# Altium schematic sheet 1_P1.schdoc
size 431 x 309 mm; Symbol: Sheet-Symbol_A3; Device: Sheet-Symbol_A3; Company: 嘉立创EDA; Version: V1.0; Page Size: A3; @Project Name: 辉光管时钟成品; @Page Count: 1; @Update Date: 2024-01-18; @Create Date: 2024-01-13; @Schematic Name: 电源部分; @Page No: 1; @Page Name: P1
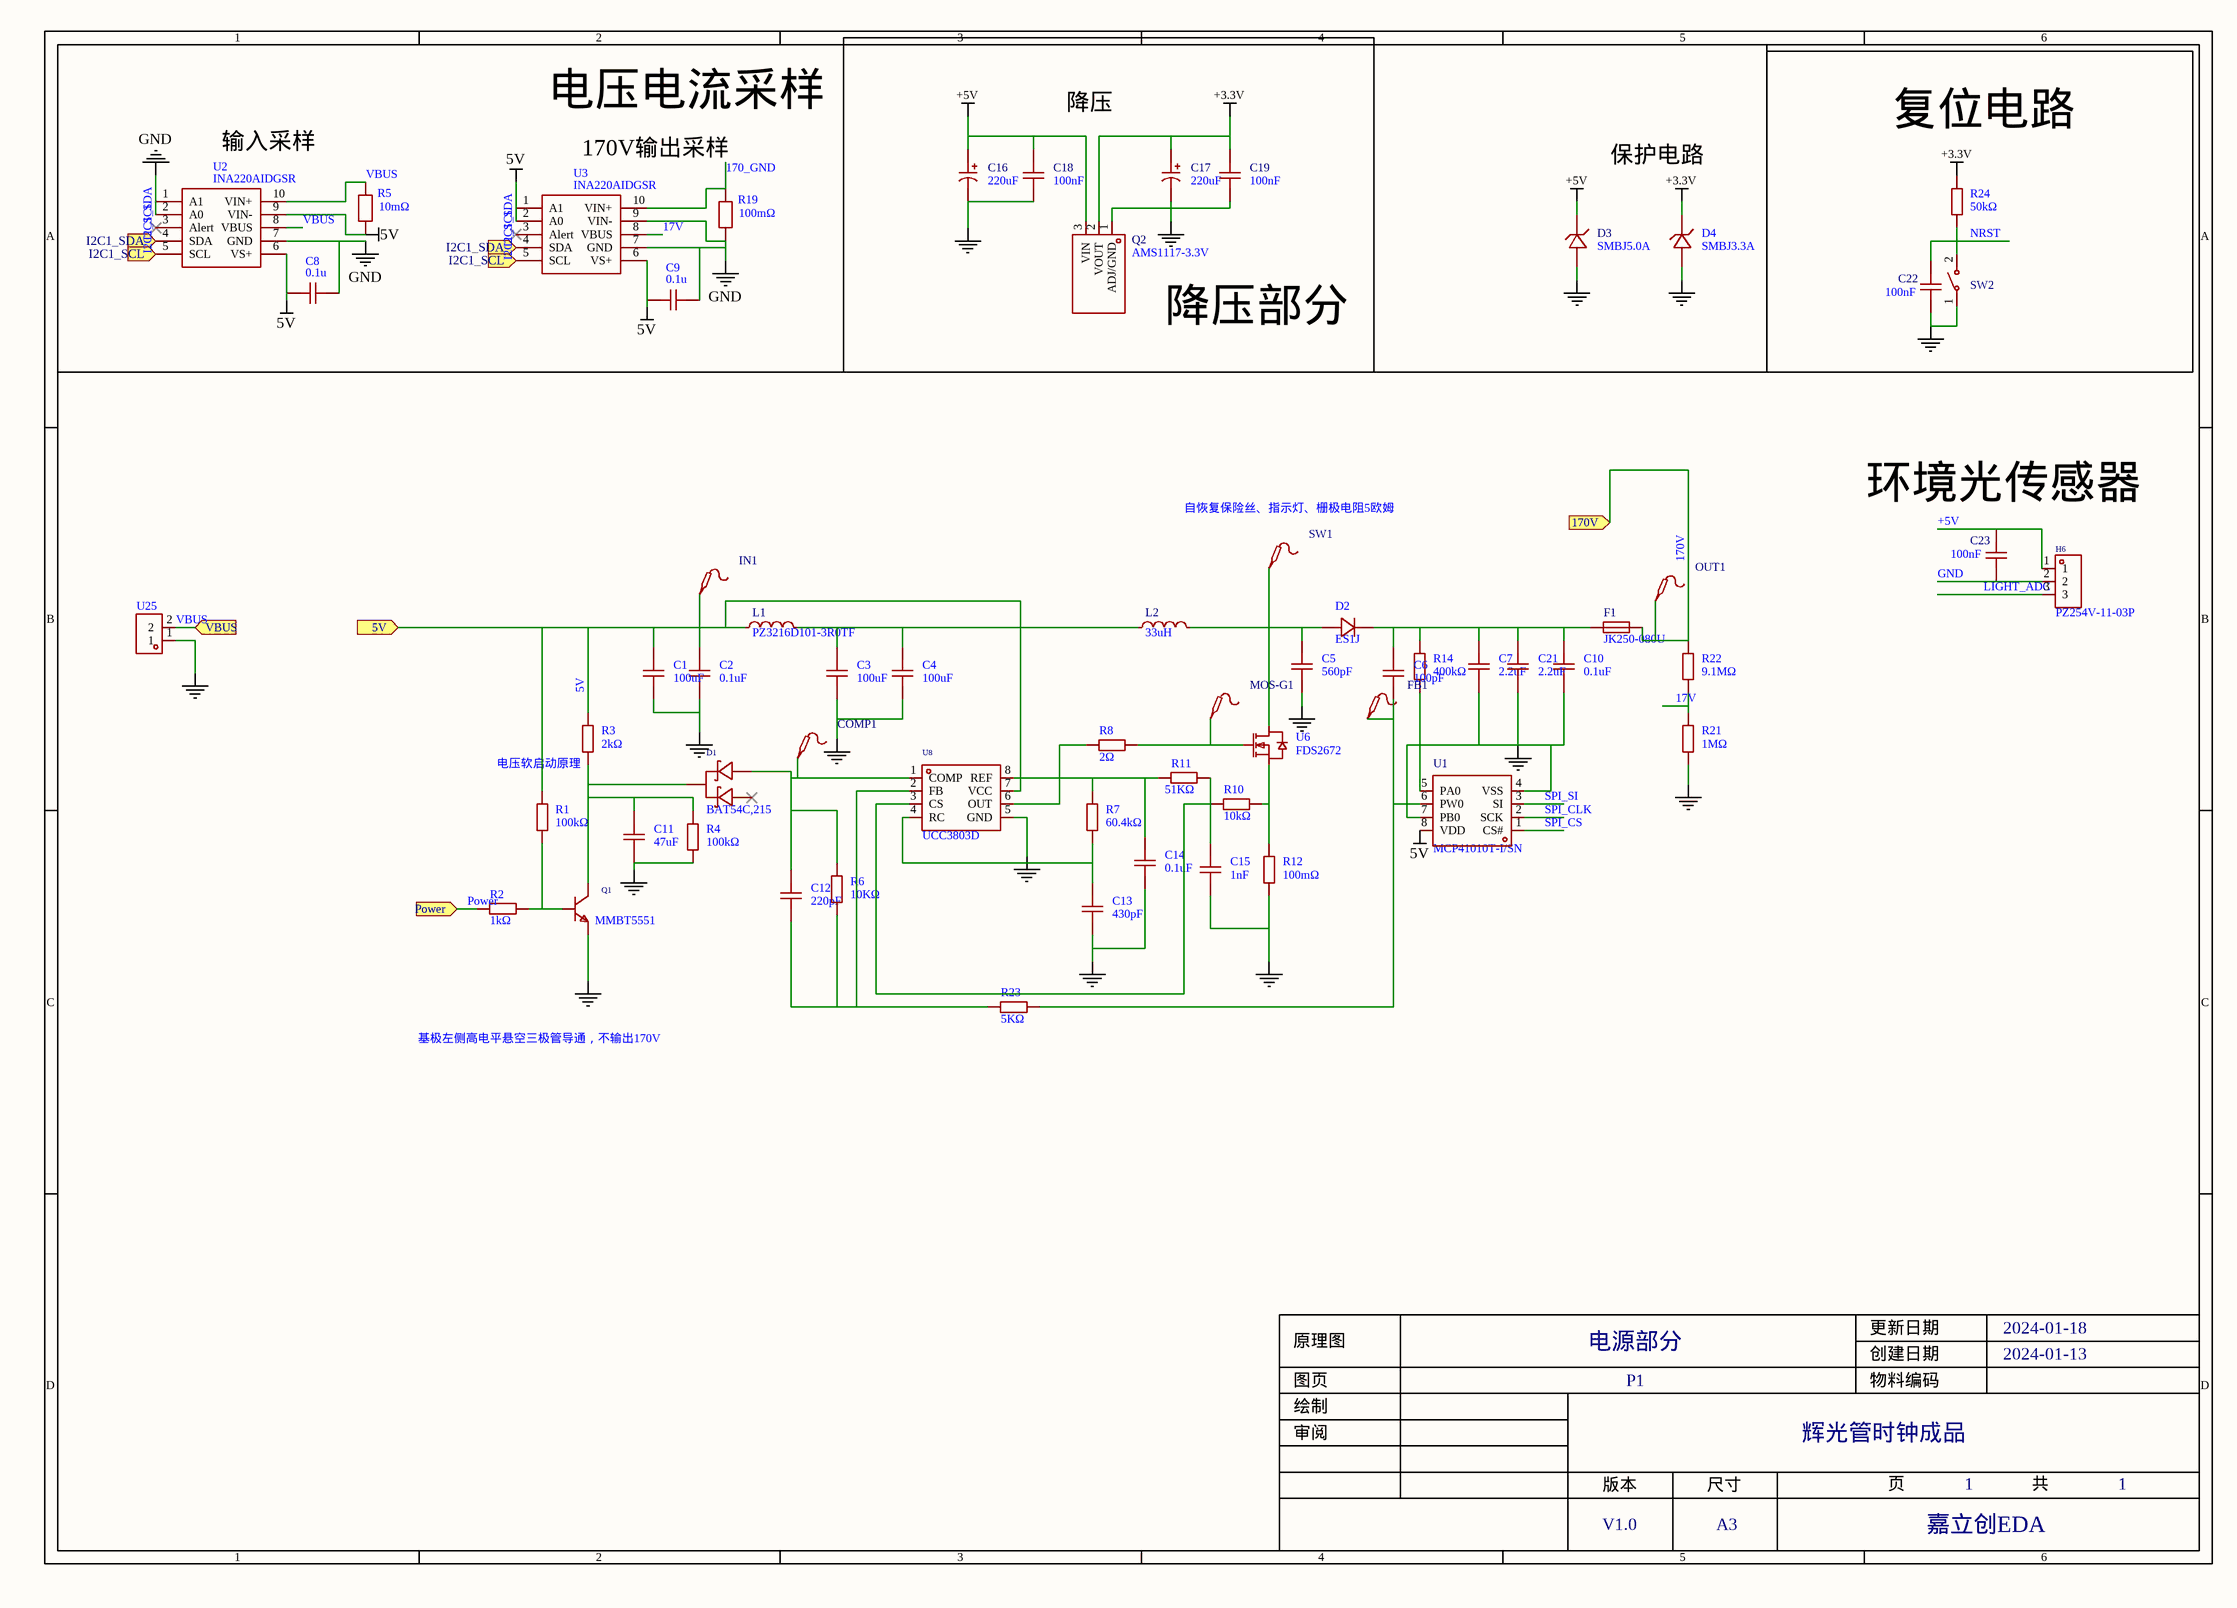
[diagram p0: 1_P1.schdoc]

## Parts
C1  100uF  [c1206]
C2  0.1uF  [c0603]
C3  100uF  [c1206]
C4  100uF  [c1206]
C5  560pF  [c1206]
C6  100pF  [C0805]
C7  2.2uF  [c1210]
C8  0.1u  [C0603]
C9  0.1u  [C0603]
C10  0.1uF  [c1206]
C11  47uF  [c0603]
C12  220pF  [c0603]
C13  430pF  [c0603]
C14  0.1uF  [c0603]
C15  1nF  [c0603]
C16  220uF  [CAP-SMD_BD6.3-L6.6-W6.6-FD]
C17  220uF  [CAP-SMD_BD6.3-L6.6-W6.6-FD]
C18  100nF  [C0603]
C19  100nF  [C0603]
C21  2.2uF  [c1210]
C22  100nF  [C0603]
C23  100nF  [C0603]
COMP1  (no value)  [Test-Point-0.5mm]
D1  BAT54C,215  [SOT-23-3_L2.9-W1.6-P1.90-LS2.8-BR]
D2  ES1J  [sod-123_l2.7-w1.6-ls3.6-rd]
D3  SMBJ5.0A  [SMB_L4.4-W3.6-LS5.3-RD]
D4  SMBJ3.3A  [SMB_L4.6-W3.6-LS5.3-RD]
F1  JK250-080U  [FUSE-TH_L5.8-W3.8-P5.10-D0.8]
FB1  (no value)  [Test-Point-0.5mm]
H6  PZ254V-11-03P  [HDR-TH_3P-P2.54-V-M]
IN1  (no value)  [Test-Point-0.5mm]
L1  PZ3216D101-3R0TF  [l0603]
L2  33uH  [33uh功率电感]
MOS-G1  (no value)  [Test-Point-0.5mm]
OUT1  (no value)  [Test-Point-0.5mm]
Q1  MMBT5551  [SOT-23-3_L2.9-W1.3-P1.90-LS2.4-BR]
Q2  AMS1117-3.3V  [SOT-89-3_L4.5-W2.5-P1.50-LS4.2-BR]
R1  100kΩ  [r0603]
R2  1kΩ  [r0603]
R3  2kΩ  [r0603]
R4  100kΩ  [r0603]
R5  10mΩ  [R0805]
R6  10KΩ  [r0603]
R7  60.4kΩ  [r0603]
R8  2Ω  [r0603]
R10  10kΩ  [r0603]
R11  51KΩ  [r0603]
R12  100mΩ  [R0805]
R14  400kΩ  [r0603]
R19  100mΩ  [R0805]
R21  1MΩ  [r0603]
R22  9.1MΩ  [r0603]
R23  5KΩ  [r0603]
R24  50kΩ  [r0603]
SW1  (no value)  [Test-Point-0.5mm]
SW2  TS-1088R-02026  [SW-SMD_L3.9-W3.0-P4.45]  (value not drawn)
U1  MCP41010T-I/SN  [SOIC-8_L4.9-W3.9-P1.27-LS6.0-BL]
U2  INA220AIDGSR  [VSSOP-10_L3.0-W3.0-P0.50-LS4.9-BL]
U3  INA220AIDGSR  [VSSOP-10_L3.0-W3.0-P0.50-LS4.9-BL]
U6  FDS2672  [SO-8_L4.9-W3.9-P1.27-LS6.0-BL]
U8  UCC3803D  [SOIC-8_L4.9-W3.9-P1.27-LS6.0-BL]
U25  (no value)  [2.54mm1*2]

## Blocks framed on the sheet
电压电流采样: C8 C9 R5 R19 U2 U3
降压部分: C16-C19 Q2
保护电路: D3 D4
复位电路: C22 R24 SW2

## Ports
5V (in), 170V (in), I2C1_SCL (in), I2C1_SDA (in), Power (in), VBUS (in)

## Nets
5V: C1.2 C2.2 C8.2 C9.2 IN1.1 L1.1 R1.2 R3.2 R5.1 U1.8(VDD) U2.6(VS+) U2.9(VIN-) U3.1(A1) U3.2(A0) U3.6(VS+) U8.7(VCC) ; port 5V
+3.3V: C17.1 C19.2 D4.1 Q2.2(VOUT) R24.2
+5V: C16.1 C18.2 C23.2 D3.1(C) H6.1 Q2.3(VIN)
GND: C1.1 C2.1 C3.1 C4.1 C5.1 C7.1 C8.1 C9.1 C10.1 C11.1 C13.1 C14.1 C15.1 C16.2 C17.2 C18.1 C19.1 C21.1 C22.1 C23.1 D3.2(A) D4.2 H6.2 Q1.2(E) Q2.1(ADJ/GND) R4.1 R12.1 R19.1 R21.2 SW2.1 U1.4(VSS) U1.7(PB0) U2.1(A1) U2.2(A0) U2.7(GND) U3.7(GND) U3.9(VIN-) U8.5(GND) U25.1
17V: R21.1 R22.2 U3.8(VBUS)
170_GND: R19.2 U3.10(VIN+)
170V: F1.2 OUT1.1 R22.1 ; port 170V
I2C1_SCL: U2.5(SCL) U3.5(SCL) ; port I2C1_SCL
I2C1_SDA: U2.4(SDA) U3.4(SDA) ; port I2C1_SDA
LIGHT_ADC: H6.3
NRST: C22.2 R24.1 SW2.2
Power: R2.2 ; port Power
SPI_CLK: U1.2(SCK)
SPI_CS: U1.1(CS#)
SPI_SI: U1.3(SI)
VBUS: R5.2 U2.8(VBUS) U2.10(VIN+) U25.2 ; port VBUS
NetC3_2: C3.2 C4.2 L1.2 L2.1
NetC5_2: C5.2 D2.2(A) L2.2 SW1.1 U6.5(D) U6.6(D) U6.7(D) U6.8(D)
NetC6_1: C6.1 FB1.1 R23.1 U1.6(PW0)
NetC6_2: C6.2 C7.2 C10.2 C21.2 D2.1(K) F1.1 R14.2
NetC11_2: C11.2 D1.3(K) Q1.3(C) R3.1 R4.2
NetC12_1: C12.1 R6.1 R23.2 U8.2(FB)
NetC12_2: C12.2 COMP1.1 D1.1(A) R6.2 U8.1(COMP)
NetC13_2: C13.2 R7.1 U8.4(RC)
NetC14_2: C14.2 R7.2 R11.2 U8.8(REF)
NetC15_2: C15.2 R10.2 R11.1 U8.3(CS)
NetMOS-G1_1: MOS-G1.1 R8.1 U6.4(G)
NetQ1_1: Q1.1(B) R1.1 R2.1
NetR8_2: R8.2 U8.6(OUT)
NetR10_1: R10.1 R12.2 U6.1(S) U6.2(S) U6.3(S)
NetR14_1: R14.1 U1.5(PA0)

Not connected (* = marked no-connect by the designer): D1 2(A)*; U2 3(Alert)*; U3 3(Alert)*

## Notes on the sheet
- 降压
- (near U2) 输入采样
- 170V输出采样
- (near SW1) 自恢复保险丝、指示灯、栅极电阻5欧姆
- (near C23) 环境光传感器
- 电压软启动原理
- 基极左侧高电平悬空三极管导通，不输出170V

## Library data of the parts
C1-C6 C10-C15 = CC0805KRX7R9BB104: Manufacturer: YAGEO(国巨); Symbol: capacitance; Add into BOM: yes; Tolerance: ±10%; Voltage Rated: 50V; Temperature Coefficient: X7R
C7 C21 = CC0805KRX7R9BB104: Manufacturer: YAGEO(国巨); Symbol: capacitance; Add into BOM: yes; Tolerance: ±10%; Voltage Rated: 200V; Temperature Coefficient: X7R
C8 C9 = 0.1u: Convert to PCB: yes
C16 C17 = RVT220UF10V67RV0037: Manufacturer: KNSCHA(科尼盛); Add into BOM: yes; Tolerance: ±20%; Rated Voltage: 10V; Ripple Current: 69mA@120Hz; φD: 6.3mm; L: 5.4mm; Lifetime @ Temp: 2000hrs@105℃
C18 C19 C22 C23 = CC0603KRX7R9BB104: Manufacturer: YAGEO(国巨); Add into BOM: yes; Tolerance: ±10%; Voltage Rated: 50V; Temperature Coefficient: X7R
COMP1 FB1 IN1 MOS-G1 OUT1 SW1 = Test-Point: Add into BOM: yes
D1 = BAT54C,215: Manufacturer: Nexperia(安世); Add into BOM: yes; Diode Configuration: 1对共阴极; Reverse Voltage (Vr): 30V; Average Rectified Current (Io): 200mA; Forward Voltage (Vf@If): 800mV@100mA; Reverse Leakage Current (Ir): 2uA@25V
D2 = ES1J_C691230: Manufacturer: DIODES(美台); Symbol: 1n4007_c9900004759; Add into BOM: yes
D3 = SMBJ5.0A_C726811: Manufacturer: TWGMC(台湾迪嘉); Add into BOM: yes
D4 = SMBJ3.3A_C362089: Manufacturer: JKSEMI(金开盛); Add into BOM: yes; Unidirectional Channels: 1; Bidirectional Channels: 0; Reverse Stand-Off Voltage (Vrwm): 3.3V; Breakdown Voltage: 4.1V; Maximum Clamping Voltage: 7.3V; Peak Pulse Power Dissipation (Ppp)@10/1000us: 600W
F1 = JK250-080U: Manufacturer: JK(金科); Symbol: JK250-080U_C369127; Add into BOM: yes; Operating Voltage (Max): 250V; Current Rating (Max): 3A; Hold Current: 80mA; Trip Current: 160mA; Maximum Time to Trip: 500ms
H6 = PZ254V-11-03P: Manufacturer: XFCN(兴飞); Symbol: PZ254V-11-03P_C2937625; Add into BOM: yes; Pitch: 2.54mm; Pin Structure: 1x3P; Circluar Pins/Square Pins: 方针; Current Rating (Max): 3A; Voltage Rating (Max): 250V
L1 = PZ3216D101-3R0TF: Manufacturer: Sunlord(顺络); Symbol: sdfl1608s100ktf; Add into BOM: yes; Impedance @ Frequency: 100Ω@100MHz; Tolerance: ±25%; Current Rating: 3A; Circuits: 1; Value: 10uH
L2 = CXP0630-330M-AG(33uh): Manufacturer: DMBJ(振宝佳); Symbol: sdfl1608s100ktf; Add into BOM: yes; Type: 一体成型电感; Tolerance: ±20%; Rated Current: 2A; Saturation Current (Isat): 2.5A; DC Resistance (DCR): 240mΩ
Q1 = MMBT5551_C2145: Manufacturer: CJ(江苏长电/长晶); Symbol: bcx70ke6327htsa1; Add into BOM: yes; Transistor Type: NPN; Collector-Emitter Breakdown Voltage (Vceo): 160V; Collector Current (Ic): 600mA; Power Dissipation (Pd): 300mW; Collector Cut-Off Current (Icbo): 50nA; Collector-Emitter Saturation Voltage (VCE(sat)@Ic,Ib): 200mV@50mA,5mA; DC Current Gain (hFE@Ic,Vce): 200@10mA,5V; Transition Frequency (fT): 100MHz
Q2 = AMS1117-3.3V_C5120796: Manufacturer: MSKSEMI(美森科); Add into BOM: yes; Output Type: 固定; Maximum Input Voltage: 18V; Output Voltage: 3.3V; MAX Output Current: 1A; Dropout Voltage: 1.4V@(1A); standby current: 12mA; Output Polarity: 正极; Number of Outputs: 1
R1-R4 R6-R8 R10 R11 R14 R21-R24 = 0805W8F1002T5E_C17414: Manufacturer: UNI-ROYAL(厚声); Symbol: 电阻; Add into BOM: yes; Tolerance: ±1%; Power(Watts): 125mW; Temperature Coefficient: ±100ppm/℃; Overload Voltage (Max): 150V
R5 R19 = 5mΩ: Convert to PCB: yes; Origin Footprint: R1206
R12 = RL10FTNR160: Manufacturer: 大毅科技; Symbol: 电阻; Add into BOM: yes; Tolerance: ±1%; Power(Watts): 125mW; Temperature Coefficient: ±100ppm/℃; Overload Voltage (Max): 150V
SW2 = TS-1088R-02026: Manufacturer: XUNPU(讯普); Add into BOM: yes; Circuit: 单刀单掷; Actuator Style: 圆形按钮; Switch Length: 3.9mm; Switch Width: 2.93mm; Switch Height: 2mm; Contact Current: 50mA; Voltage Rating (DC): 12V
U1 = MCP41010T-I/SN: Manufacturer: MICROCHIP(美国微芯); Add into BOM: yes; Supply Voltage: 2.7V~5.5V; Resistance Value (Ohms): 10kΩ; Number of Taps: 256; Temperature Coefficient (Typ): 800ppm/℃; Precision: ±20%; Number of Channels: 1; Interface Type: SPI
U2 U3 = INA220AIDGSR: Manufacturer: TI(德州仪器); Symbol: INA220; Add into BOM: yes; Origin Footprint: MSOP-10_L3.0-W3.0-P0.50-LS5.0-BL
U6 = FDS2672: Manufacturer: onsemi(安森美); Add into BOM: yes; Drain Source Voltage (Vdss): 200V; Continuous Drain Current (Id): 3.9A; Power Dissipation (Pd): 2.5W; Drain Source On Resistance (RDS(on)@Vgs,Id): 70mΩ@10V,3.9A; Gate Threshold Voltage (Vgs(th)@Id): 4V@250uA; Total Gate Charge (Qg@Vgs): 46nC@10V; Input Capacitance (Ciss@Vds): 2.535nF@100V
U8 = UCC3803D: Manufacturer: TI(德州仪器); Symbol: ucc3803dtrg4; Add into BOM: yes; Function: 升压型；降压型；升降压型; Number of Outputs: 1; Input Voltage: 3.6V~12V; Synchronous Rectification: 否; Topology: 反激式；降压式；正激式；升压式; Switching Frequency: 31kHz; Duty Cycle (Max): 99%
U25 = 排针: Add into BOM: yes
